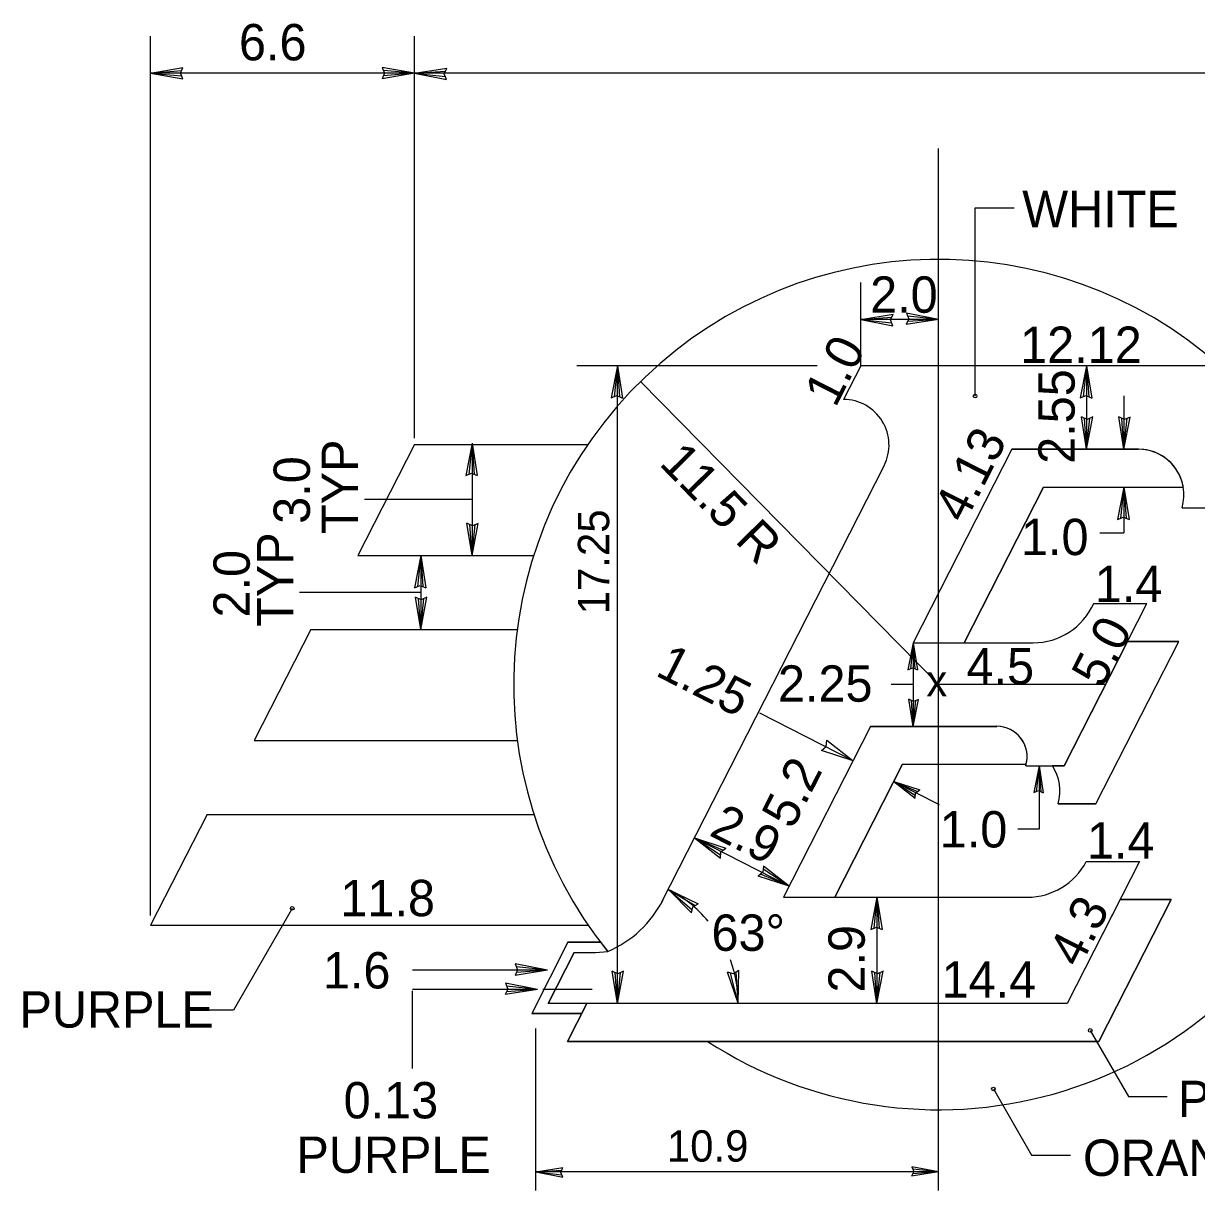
# Model space of a CAD drawing. Extents: x 10268197 to 10269179, y 2141503 to 2142677.
# Drawn here: x 10268853.69 to 10268876.28, y 2142091 to 2142113.47 of the extents above; entities that cross this region are included whole.
import ezdxf

# ---------------------------------------------------------------- set-up
doc = ezdxf.new("R2010")
doc.units = 0
for name, color, linetype in [('1', 7, 'Continuous'), ('2', 7, 'Continuous'), ('20', 7, 'Continuous'), ('21', 7, 'Continuous'), ('3', 7, 'Continuous'), ('52', 7, 'Continuous')]:
    doc.layers.add(name, color=color, linetype=linetype)

msp = doc.modelspace()

# ---------------------------------------------------------------- linework, layer by layer
at = {"layer": '1'}
for p, q in [((10268871.316, 2142100.743), (10268871.316, 2142111.065)), ((10268869.814, 2142106.882), (10268869.482, 2142106.232)), ((10268878.438, 2142106.882), (10268869.814, 2142106.882)), ((10268871.316, 2142100.743), (10268865.571, 2142106.576)), ((10268861.216, 2142105.363), (10268860.128, 2142103.227)), ((10268861.216, 2142105.363), (10268864.558, 2142105.363)), ((10268872.724, 2142105.275), (10268870.825, 2142101.546)), ((10268872.724, 2142105.275), (10268870.825, 2142101.546)), ((10268872.724, 2142105.275), (10268875.164, 2142105.275)), ((10268875.164, 2142105.275), (10268872.724, 2142105.275)), ((10268865.986, 2142096.559), (10268870.265, 2142104.957)), ((10268873.336, 2142104.544), (10268871.808, 2142101.546)), ((10268871.808, 2142101.546), (10268873.336, 2142104.544)), ((10268873.336, 2142104.544), (10268876.029, 2142104.544)), ((10268873.336, 2142104.544), (10268876.029, 2142104.544)), ((10268862.327, 2142104.309), (10268860.256, 2142104.309)), ((10268876.005, 2142104.148), (10268877.045, 2142104.148)), ((10268860.128, 2142103.227), (10268863.516, 2142103.227)), ((10268861.338, 2142102.515), (10268859.002, 2142102.515)), ((10268873.735, 2142099.179), (10268875.327, 2142102.306)), ((10268874.302, 2142102.306), (10268875.327, 2142102.306)), ((10268859.221, 2142101.803), (10268858.132, 2142099.668)), ((10268859.221, 2142101.803), (10268863.198, 2142101.803)), ((10268874.955, 2142101.574), (10268873.735, 2142099.179)), ((10268874.347, 2142098.448), (10268875.94, 2142101.575)), ((10268874.347, 2142098.448), (10268875.94, 2142101.575)), ((10268874.955, 2142101.574), (10268875.94, 2142101.575)), ((10268875.94, 2142101.575), (10268874.955, 2142101.574)), ((10268870.825, 2142101.546), (10268873.137, 2142101.546)), ((10268870.825, 2142101.546), (10268871.808, 2142101.546)), ((10268870.825, 2142100.742), (10268870.4, 2142100.742)), ((10268871.316, 2142091.001), (10268871.316, 2142100.743)), ((10268874.531, 2142100.743), (10268871.316, 2142100.743)), ((10268870.006, 2142099.938), (10268868.33, 2142096.649)), ((10268870.006, 2142099.938), (10268868.33, 2142096.649)), ((10268870.006, 2142099.938), (10268872.436, 2142099.938)), ((10268872.436, 2142099.938), (10268870.006, 2142099.938)), ((10268858.132, 2142099.668), (10268863.2, 2142099.668)), ((10268870.617, 2142099.208), (10268869.314, 2142096.649)), ((10268869.314, 2142096.649), (10268870.617, 2142099.208)), ((10268870.617, 2142099.208), (10268873.003, 2142099.208)), ((10268870.617, 2142099.208), (10268873.003, 2142099.208)), ((10268872.994, 2142099.179), (10268873.735, 2142099.179)), ((10268873.735, 2142099.179), (10268873.508, 2142099.18)), ((10268874.347, 2142098.448), (10268873.615, 2142098.448)), ((10268873.615, 2142098.448), (10268874.347, 2142098.448)), ((10268857.225, 2142098.244), (10268856.136, 2142096.108)), ((10268857.225, 2142098.244), (10268863.52, 2142098.244)), ((10268875.184, 2142097.338), (10268873.79, 2142094.602)), ((10268874.16, 2142097.338), (10268875.184, 2142097.338)), ((10268868.33, 2142096.649), (10268873.026, 2142096.649)), ((10268868.33, 2142096.649), (10268869.314, 2142096.649)), ((10268874.812, 2142096.607), (10268873.79, 2142094.602)), ((10268875.796, 2142096.606), (10268874.402, 2142093.871)), ((10268874.402, 2142093.871), (10268875.796, 2142096.606)), ((10268874.812, 2142096.607), (10268875.796, 2142096.606)), ((10268875.796, 2142096.606), (10268874.812, 2142096.607)), ((10268856.136, 2142096.108), (10268864.567, 2142096.108)), ((10268873.79, 2142094.602), (10268863.794, 2142094.602)), ((10268864.168, 2142093.871), (10268864.54, 2142094.602)), ((10268864.54, 2142094.602), (10268864.168, 2142093.871)), ((10268873.79, 2142094.602), (10268864.54, 2142094.602)), ((10268864.441, 2142094.407), (10268863.476, 2142094.407)), ((10268863.557, 2142091.001), (10268863.557, 2142094.12)), ((10268874.402, 2142093.871), (10268864.168, 2142093.871)), ((10268864.168, 2142093.871), (10268874.402, 2142093.871))]:
    msp.add_line(p, q, dxfattribs=at)
for centre, radius, start, end in [((10268871.316, 2142100.743), 8.187, 48.5904, 218.8792), ((10268869.483, 2142105.355), 0.877, 333.0033, 90.1042), ((10268875.165, 2142104.397), 0.877, 343.4611, 90), ((10268875.165, 2142104.397), 0.877, 9.5941, 90), ((10268873.138, 2142102.819), 1.272, 270, 336.2493), ((10268872.436, 2142099.354), 0.585, 342.6625, 90), ((10268872.436, 2142099.354), 0.585, 345.5225, 90), ((10268872.775, 2142098.698), 0.877, 343.4611, 33.2756), ((10268872.775, 2142098.698), 0.877, 343.4611, 33.2756), ((10268873.026, 2142097.928), 1.279, 270, 332.5096), ((10268871.316, 2142100.743), 8.187, 237.0648, 334.1734), ((10268864.103, 2142097.568), 2.136, 293.1567, 333.0112)]:
    msp.add_arc(centre, radius, start, end, dxfattribs=at)
at = {"layer": '2'}
for p, q in [((10268864.174, 2142095.78), (10268863.476, 2142094.407)), ((10268864.174, 2142095.78), (10268864.811, 2142095.78)), ((10268864.294, 2142095.585), (10268863.794, 2142094.602))]:
    msp.add_line(p, q, dxfattribs=at)
at = {"layer": '20'}
for p, q in [((10268856.136, 2142096.298), (10268856.136, 2142113.226)), ((10268861.217, 2142106.525), (10268861.216, 2142113.226)), ((10268861.216, 2142112.514), (10268856.136, 2142112.514)), ((10268908.253, 2142112.514), (10268861.216, 2142112.514)), ((10268872.018, 2142106.298), (10268872.018, 2142109.921)), ((10268872.018, 2142109.921), (10268872.768, 2142109.921)), ((10268869.814, 2142106.882), (10268869.814, 2142108.485)), ((10268871.316, 2142107.773), (10268869.814, 2142107.773)), ((10268868.976, 2142106.882), (10268864.345, 2142106.883)), ((10268865.126, 2142094.602), (10268865.126, 2142106.882)), ((10268874.165, 2142106.882), (10268874.165, 2142105.275)), ((10268861.217, 2142105.487), (10268861.217, 2142106.525)), ((10268874.884, 2142106.301), (10268874.884, 2142105.275)), ((10268862.327, 2142105.39), (10268862.327, 2142103.227)), ((10268874.884, 2142104.544), (10268874.884, 2142103.667)), ((10268874.42, 2142103.667), (10268874.884, 2142103.667)), ((10268861.338, 2142103.227), (10268861.339, 2142101.803)), ((10268870.825, 2142101.546), (10268870.825, 2142099.938)), ((10268869.669, 2142099.276), (10268867.869, 2142100.193)), ((10268873.249, 2142099.179), (10268873.249, 2142097.956)), ((10268870.45, 2142098.878), (10268871.324, 2142098.432)), ((10268873.249, 2142097.956), (10268872.841, 2142097.956)), ((10268866.613, 2142097.79), (10268868.438, 2142096.861)), ((10268870.128, 2142096.649), (10268870.128, 2142094.602)), ((10268858.863, 2142096.434), (10268857.731, 2142094.473)), ((10268863.779, 2142095.243), (10268861.182, 2142095.243)), ((10268863.59, 2142094.871), (10268861.182, 2142094.871)), ((10268861.182, 2142093.351), (10268861.182, 2142094.848)), ((10268864.641, 2142094.871), (10268863.694, 2142094.871)), ((10268857.731, 2142094.473), (10268856.981, 2142094.473)), ((10268874.237, 2142094.084), (10268874.971, 2142092.813)), ((10268872.37, 2142092.956), (10268873.104, 2142091.684)), ((10268874.971, 2142092.813), (10268875.721, 2142092.813)), ((10268873.104, 2142091.684), (10268873.854, 2142091.684)), ((10268871.316, 2142091.358), (10268863.557, 2142091.358))]:
    msp.add_line(p, q, dxfattribs=at)
for centre in [(10268872.018, 2142106.298), (10268858.863, 2142096.434), (10268874.237, 2142094.084), (10268872.37, 2142092.956)]:
    msp.add_circle(centre, 0.0356, dxfattribs=at)
for start, end in [(40.0298, 62.999), (0, 19.9667)]:
    msp.add_arc((10268864.989, 2142094.602), 2.465, start, end, dxfattribs=at)
at = {"layer": '21'}
for p, q in [((10268856.136, 2142112.514), (10268856.758, 2142112.623)), ((10268856.136, 2142112.514), (10268856.732, 2142112.566)), ((10268856.136, 2142112.514), (10268856.758, 2142112.404)), ((10268856.136, 2142112.514), (10268856.733, 2142112.462)), ((10268856.71, 2142112.514), (10268856.758, 2142112.623)), ((10268856.758, 2142112.404), (10268856.71, 2142112.514)), ((10268861.216, 2142112.514), (10268860.594, 2142112.623)), ((10268860.594, 2142112.623), (10268860.642, 2142112.514)), ((10268861.216, 2142112.514), (10268860.594, 2142112.404)), ((10268860.642, 2142112.514), (10268860.594, 2142112.404)), ((10268861.216, 2142112.514), (10268860.619, 2142112.566)), ((10268861.216, 2142112.514), (10268860.62, 2142112.462)), ((10268861.216, 2142112.514), (10268861.84, 2142112.613)), ((10268861.216, 2142112.514), (10268861.813, 2142112.555)), ((10268861.216, 2142112.514), (10268861.836, 2142112.393)), ((10268861.216, 2142112.514), (10268861.812, 2142112.451)), ((10268861.79, 2142112.504), (10268861.84, 2142112.613)), ((10268861.836, 2142112.393), (10268861.79, 2142112.504)), ((10268871.316, 2142107.773), (10268870.696, 2142107.893)), ((10268870.696, 2142107.893), (10268870.742, 2142107.783)), ((10268869.814, 2142107.773), (10268870.437, 2142107.872)), ((10268869.814, 2142107.773), (10268870.411, 2142107.815)), ((10268869.814, 2142107.773), (10268870.433, 2142107.653)), ((10268869.814, 2142107.773), (10268870.409, 2142107.711)), ((10268870.388, 2142107.763), (10268870.437, 2142107.872)), ((10268870.433, 2142107.653), (10268870.388, 2142107.763)), ((10268870.742, 2142107.783), (10268870.693, 2142107.674)), ((10268871.316, 2142107.773), (10268870.693, 2142107.674)), ((10268871.316, 2142107.773), (10268870.719, 2142107.731)), ((10268871.316, 2142107.773), (10268870.72, 2142107.835)), ((10268865.126, 2142106.882), (10268865.005, 2142106.262)), ((10268865.126, 2142106.882), (10268865.063, 2142106.286)), ((10268865.126, 2142106.882), (10268865.225, 2142106.258)), ((10268865.126, 2142106.882), (10268865.167, 2142106.285)), ((10268874.165, 2142106.882), (10268874.044, 2142106.262)), ((10268874.165, 2142106.882), (10268874.102, 2142106.286)), ((10268874.165, 2142106.882), (10268874.264, 2142106.258)), ((10268874.165, 2142106.882), (10268874.206, 2142106.285)), ((10268865.005, 2142106.262), (10268865.116, 2142106.308)), ((10268865.116, 2142106.308), (10268865.225, 2142106.258)), ((10268874.044, 2142106.262), (10268874.155, 2142106.308)), ((10268874.155, 2142106.308), (10268874.264, 2142106.258)), ((10268874.165, 2142105.275), (10268874.066, 2142105.898)), ((10268874.175, 2142105.849), (10268874.066, 2142105.898)), ((10268874.165, 2142105.275), (10268874.123, 2142105.872)), ((10268874.165, 2142105.275), (10268874.285, 2142105.895)), ((10268874.165, 2142105.275), (10268874.227, 2142105.871)), ((10268874.285, 2142105.895), (10268874.175, 2142105.849)), ((10268874.884, 2142105.275), (10268874.785, 2142105.898)), ((10268874.894, 2142105.849), (10268874.785, 2142105.898)), ((10268874.884, 2142105.275), (10268874.842, 2142105.872)), ((10268874.884, 2142105.275), (10268875.004, 2142105.894)), ((10268874.884, 2142105.275), (10268874.946, 2142105.871)), ((10268875.004, 2142105.894), (10268874.894, 2142105.849)), ((10268862.327, 2142105.39), (10268862.207, 2142104.77)), ((10268862.327, 2142105.39), (10268862.264, 2142104.794)), ((10268862.327, 2142105.39), (10268862.426, 2142104.766)), ((10268862.327, 2142105.39), (10268862.368, 2142104.793)), ((10268862.207, 2142104.77), (10268862.317, 2142104.816)), ((10268862.317, 2142104.816), (10268862.426, 2142104.766)), ((10268874.884, 2142104.544), (10268874.763, 2142103.924)), ((10268874.884, 2142104.544), (10268874.821, 2142103.948)), ((10268874.884, 2142104.544), (10268874.983, 2142103.92)), ((10268874.884, 2142104.544), (10268874.925, 2142103.946)), ((10268862.327, 2142103.227), (10268862.228, 2142103.851)), ((10268862.337, 2142103.801), (10268862.228, 2142103.851)), ((10268862.327, 2142103.227), (10268862.285, 2142103.825)), ((10268862.327, 2142103.227), (10268862.447, 2142103.847)), ((10268862.327, 2142103.227), (10268862.389, 2142103.823)), ((10268862.447, 2142103.847), (10268862.337, 2142103.801)), ((10268874.763, 2142103.924), (10268874.874, 2142103.969)), ((10268874.874, 2142103.969), (10268874.983, 2142103.92)), ((10268861.338, 2142103.227), (10268861.218, 2142102.607)), ((10268861.338, 2142103.227), (10268861.276, 2142102.631)), ((10268861.338, 2142103.227), (10268861.437, 2142102.604)), ((10268861.338, 2142103.227), (10268861.38, 2142102.63)), ((10268861.218, 2142102.607), (10268861.328, 2142102.653)), ((10268861.328, 2142102.653), (10268861.437, 2142102.604)), ((10268861.339, 2142101.803), (10268861.239, 2142102.427)), ((10268861.348, 2142102.377), (10268861.239, 2142102.427)), ((10268861.339, 2142101.803), (10268861.296, 2142102.401)), ((10268861.339, 2142101.803), (10268861.459, 2142102.423)), ((10268861.339, 2142101.803), (10268861.401, 2142102.399)), ((10268861.459, 2142102.423), (10268861.348, 2142102.377)), ((10268870.825, 2142101.546), (10268870.725, 2142101.029)), ((10268870.825, 2142101.546), (10268870.774, 2142101.049)), ((10268870.825, 2142101.546), (10268870.908, 2142101.026)), ((10268870.825, 2142101.546), (10268870.86, 2142101.048)), ((10268870.725, 2142101.029), (10268870.818, 2142101.067)), ((10268870.818, 2142101.067), (10268870.908, 2142101.026)), ((10268870.825, 2142099.938), (10268870.743, 2142100.459)), ((10268870.834, 2142100.418), (10268870.743, 2142100.459)), ((10268870.825, 2142099.938), (10268870.79, 2142100.437)), ((10268870.825, 2142099.938), (10268870.926, 2142100.455)), ((10268870.825, 2142099.938), (10268870.877, 2142100.435)), ((10268870.926, 2142100.455), (10268870.834, 2142100.418)), ((10268873.249, 2142099.179), (10268873.149, 2142098.662)), ((10268873.249, 2142099.179), (10268873.197, 2142098.682)), ((10268873.249, 2142099.179), (10268873.332, 2142098.659)), ((10268873.249, 2142099.179), (10268873.284, 2142098.681)), ((10268870.45, 2142098.878), (10268870.951, 2142098.716)), ((10268870.45, 2142098.878), (10268870.865, 2142098.554)), ((10268870.45, 2142098.878), (10268870.869, 2142098.607)), ((10268870.45, 2142098.878), (10268870.909, 2142098.683)), ((10268870.865, 2142098.554), (10268870.873, 2142098.653)), ((10268870.873, 2142098.653), (10268870.951, 2142098.716)), ((10268873.149, 2142098.662), (10268873.241, 2142098.7)), ((10268873.241, 2142098.7), (10268873.332, 2142098.659)), ((10268866.613, 2142097.79), (10268867.214, 2142097.595)), ((10268866.613, 2142097.79), (10268867.111, 2142097.402)), ((10268866.613, 2142097.79), (10268867.116, 2142097.464)), ((10268866.613, 2142097.79), (10268867.165, 2142097.556)), ((10268867.111, 2142097.402), (10268867.121, 2142097.521)), ((10268867.121, 2142097.521), (10268867.214, 2142097.595)), ((10268867.931, 2142097.13), (10268867.837, 2142097.056)), ((10268868.438, 2142096.861), (10268867.837, 2142097.056)), ((10268868.438, 2142096.861), (10268867.887, 2142097.095)), ((10268867.94, 2142097.249), (10268867.931, 2142097.13)), ((10268868.438, 2142096.861), (10268867.935, 2142097.187)), ((10268868.438, 2142096.861), (10268867.94, 2142097.249)), ((10268866.112, 2142096.798), (10268866.68, 2142096.524)), ((10268866.112, 2142096.798), (10268866.552, 2142096.346)), ((10268866.112, 2142096.798), (10268866.566, 2142096.407)), ((10268866.112, 2142096.798), (10268866.626, 2142096.492)), ((10268870.128, 2142096.649), (10268870.007, 2142096.029)), ((10268870.128, 2142096.649), (10268870.065, 2142096.053)), ((10268870.128, 2142096.649), (10268870.227, 2142096.025)), ((10268870.128, 2142096.649), (10268870.169, 2142096.051)), ((10268866.552, 2142096.346), (10268866.578, 2142096.463)), ((10268866.578, 2142096.463), (10268866.68, 2142096.524)), ((10268870.007, 2142096.029), (10268870.118, 2142096.074)), ((10268870.118, 2142096.074), (10268870.227, 2142096.025)), ((10268863.205, 2142095.253), (10268863.155, 2142095.144)), ((10268863.779, 2142095.243), (10268863.155, 2142095.144)), ((10268863.779, 2142095.243), (10268863.159, 2142095.364)), ((10268863.159, 2142095.364), (10268863.205, 2142095.253)), ((10268863.779, 2142095.243), (10268863.182, 2142095.201)), ((10268863.779, 2142095.243), (10268863.183, 2142095.306)), ((10268867.465, 2142095.238), (10268867.364, 2142095.174)), ((10268867.454, 2142094.606), (10268867.465, 2142095.238)), ((10268865.126, 2142094.602), (10268865.027, 2142095.226)), ((10268865.136, 2142095.176), (10268865.027, 2142095.226)), ((10268865.126, 2142094.602), (10268865.084, 2142095.199)), ((10268865.126, 2142094.602), (10268865.246, 2142095.222)), ((10268865.126, 2142094.602), (10268865.188, 2142095.198)), ((10268865.246, 2142095.222), (10268865.136, 2142095.176)), ((10268867.454, 2142094.606), (10268867.248, 2142095.203)), ((10268867.364, 2142095.174), (10268867.248, 2142095.203)), ((10268867.454, 2142094.606), (10268867.309, 2142095.187)), ((10268867.454, 2142094.606), (10268867.412, 2142095.204)), ((10268870.128, 2142094.602), (10268870.029, 2142095.226)), ((10268870.137, 2142095.176), (10268870.029, 2142095.226)), ((10268870.128, 2142094.602), (10268870.086, 2142095.199)), ((10268870.128, 2142094.602), (10268870.248, 2142095.222)), ((10268870.128, 2142094.602), (10268870.19, 2142095.198)), ((10268870.248, 2142095.222), (10268870.137, 2142095.176)), ((10268863.015, 2142094.881), (10268862.966, 2142094.772)), ((10268863.59, 2142094.871), (10268862.966, 2142094.772)), ((10268863.59, 2142094.871), (10268862.97, 2142094.991)), ((10268862.97, 2142094.991), (10268863.015, 2142094.881)), ((10268863.59, 2142094.871), (10268862.992, 2142094.829)), ((10268863.59, 2142094.871), (10268862.994, 2142094.933)), ((10268863.557, 2142091.358), (10268864.077, 2142091.441)), ((10268863.557, 2142091.358), (10268864.055, 2142091.393)), ((10268864.035, 2142091.35), (10268864.077, 2142091.441)), ((10268871.316, 2142091.358), (10268870.799, 2142091.459)), ((10268870.799, 2142091.459), (10268870.837, 2142091.367)), ((10268871.316, 2142091.358), (10268870.819, 2142091.411)), ((10268863.557, 2142091.358), (10268864.074, 2142091.258)), ((10268863.557, 2142091.358), (10268864.054, 2142091.306)), ((10268864.074, 2142091.258), (10268864.035, 2142091.35)), ((10268870.837, 2142091.367), (10268870.796, 2142091.276)), ((10268871.316, 2142091.358), (10268870.796, 2142091.276)), ((10268871.316, 2142091.358), (10268870.818, 2142091.324))]:
    msp.add_line(p, q, dxfattribs=at)
at = {"layer": '3'}
for p, q in [((10268864.294, 2142095.585), (10268864.704, 2142095.585)), ((10268864.704, 2142095.585), (10268864.943, 2142095.604))]:
    msp.add_line(p, q, dxfattribs=at)
msp.add_lwpolyline([(10268864.811, 2142095.78), (10268864.174, 2142095.78), (10268863.476, 2142094.407), (10268864.441, 2142094.407), (10268864.54, 2142094.602), (10268863.794, 2142094.602), (10268864.294, 2142095.585), (10268864.704, 2142095.585), (10268864.943, 2142095.604)], close=True, dxfattribs=at)
at = {"layer": '52'}
msp.add_lwpolyline([(10268869.669, 2142099.276), (10268869.056, 2142099.475), (10268869.148, 2142099.551), (10268869.161, 2142099.671)], close=True, dxfattribs=at)

# ---------------------------------------------------------------- texts
at = {"layer": '1'}
msp.add_text('x', height=0.604, dxfattribs=at).set_placement((10268871.078, 2142100.515))
at = {"layer": '20'}
for s, height, p in [('6.6', 0.7, (10268857.837, 2142112.762)), ('WHITE', 0.7, (10268872.926, 2142109.55)), ('2.0', 0.7, (10268869.996, 2142107.902)), ('12.12', 0.7, (10268872.886, 2142106.936)), ('1.0', 0.7, (10268872.902, 2142103.235)), ('1.4', 0.7, (10268874.324, 2142102.33)), ('4.5', 0.7, (10268871.853, 2142100.748)), ('1.0', 0.7, (10268871.337, 2142097.606)), ('1.4', 0.7, (10268874.174, 2142097.391)), ('11.8', 0.7, (10268859.791, 2142096.283)), ('63°', 0.7, (10268866.94, 2142095.616)), ('1.6', 0.7, (10268859.454, 2142094.891)), ('14.4', 0.7, (10268871.372, 2142094.716)), ('PURPLE', 0.7, (10268853.609, 2142094.137)), ('0.13', 0.7, (10268859.853, 2142092.39)), ('PURPLE', 0.7, (10268875.925, 2142092.415)), ('10.9', 0.6037, (10268866.08, 2142091.557)), ('PURPLE', 0.7, (10268858.944, 2142091.34)), ('ORANGE', 0.7, (10268874.096, 2142091.282))]:
    msp.add_text(s, height=height, dxfattribs=at).set_placement(p)
for s, height, rotation, p in [('1.0', 0.7, 62.9854, (10268869.327, 2142106.058)), ('2.55', 0.7, 90, (10268873.936, 2142104.993)), ('4.13', 0.7, 63.012, (10268871.816, 2142103.824)), ('TYP', 0.7, 90, (10268860.13, 2142103.641)), ('11.5 R', 0.7, 314.5624, (10268865.913, 2142104.982)), ('3.0', 0.7, 90, (10268859.204, 2142103.838)), ('17.25', 0.6037, 90, (10268864.969, 2142102.095)), ('TYP', 0.7, 90, (10268858.883, 2142101.853)), ('2.0', 0.7, 90, (10268858.045, 2142102.033)), ('5.0', 0.7, 63.0087, (10268874.468, 2142100.649)), ('1.25', 0.7, 333.0041, (10268865.837, 2142100.929)), ('2.25', 0.7, 360, (10268868.22, 2142100.413)), ('5.2', 0.7, 63.0001, (10268868.5, 2142097.935)), ('2.9', 0.7, 333.0028, (10268866.873, 2142097.85)), ('4.3', 0.7, 62.9952, (10268874.029, 2142095.267)), ('2.9', 0.7, 90, (10268869.892, 2142094.812))]:
    msp.add_text(s, height=height, rotation=rotation, dxfattribs=at).set_placement(p)

doc.saveas('drawing.dxf')
